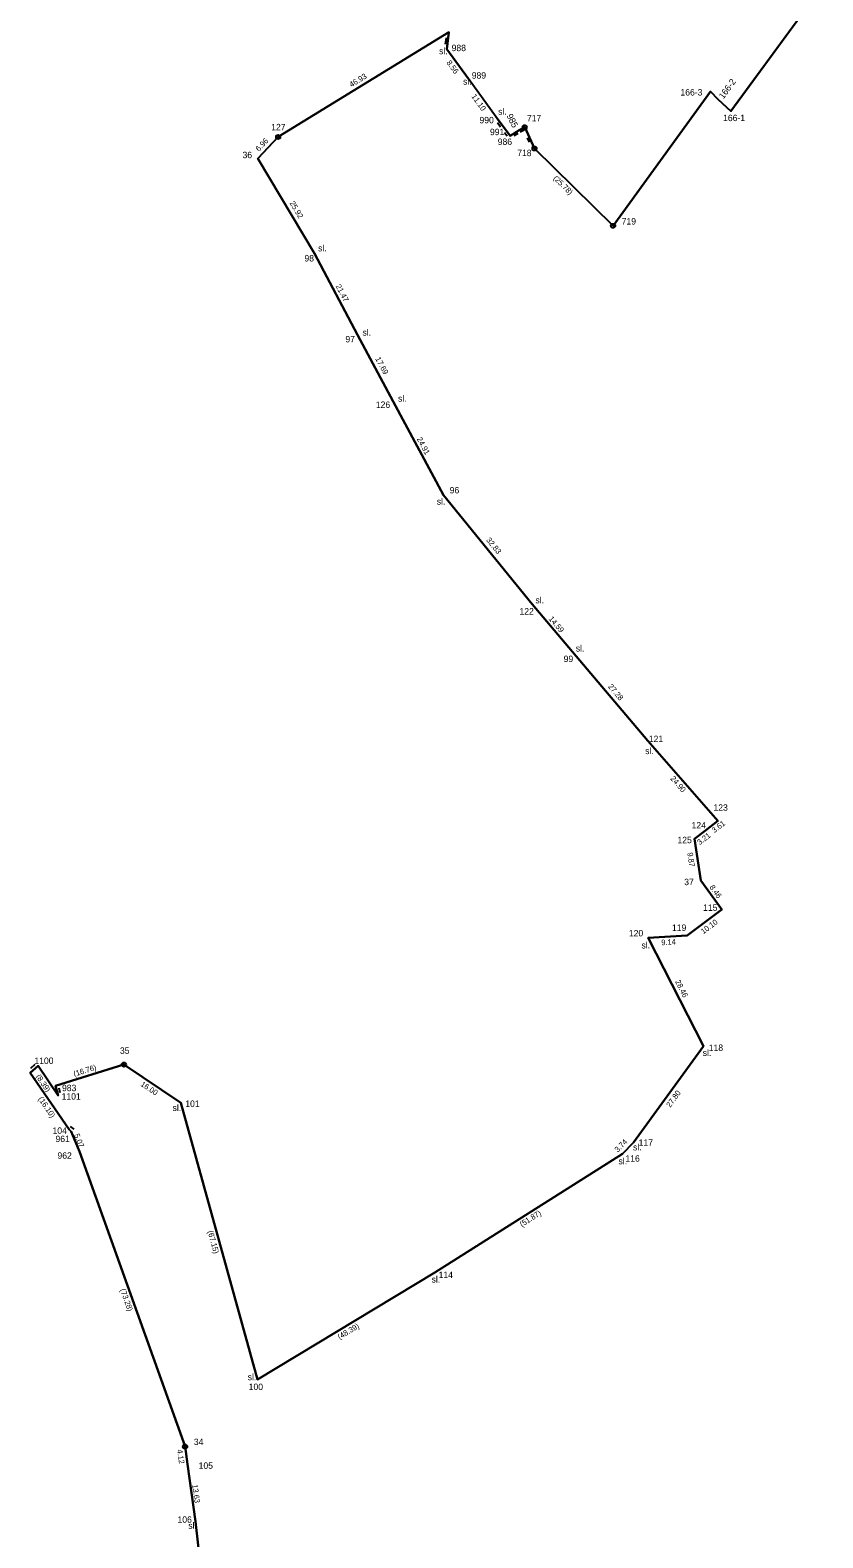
# Model space of a CAD drawing. Extents: x -555170 to -550532, y -1039598 to -1034701.
# Drawn here: x -553408.5 to -553223.3, y -1037142.8 to -1036790.2 of the extents above; entities that cross this region are included whole.
import ezdxf

# ---------------------------------------------------------------- set-up
doc = ezdxf.new("R2010")
doc.units = 0
for name, color, linetype in [('Vrstva 10', 7, 'Continuous'), ('Vrstva 40', 7, 'Continuous'), ('Vrstva 43', 7, 'Continuous'), ('Vrstva 48', 7, 'Continuous')]:
    doc.layers.add(name, color=color, linetype=linetype)

msp = doc.modelspace()

# ---------------------------------------------------------------- linework, layer by layer
at = {"layer": 'Vrstva 10'}
for p, q in [((-553311.34, -1036792.05), (-553311.51, -1036793.49)), ((-553299.35, -1036811.86), (-553298.6, -1036812.89)), ((-553297.7, -1036814.18), (-553297.09, -1036814.97)), ((-553294.55, -1036814.4), (-553295.49, -1036814.99)), ((-553293.06, -1036813.64), (-553293.98, -1036814.12)), ((-553292.37, -1036815.42), (-553291.94, -1036816.44)), ((-553407.46, -1037032.17), (-553408.45, -1037033.06)), ((-553401.8, -1037037.58), (-553401.57, -1037038.7)), ((-553398.25, -1037047.28), (-553399.1, -1037046.63))]:
    msp.add_line(p, q, dxfattribs=at)
at = {"layer": 'Vrstva 40'}
for p, q in [((-553244.82, -1036809.16), (-553223.29, -1036779.77)), ((-553350.57, -1036815.23), (-553310.65, -1036790.68)), ((-553310.65, -1036790.68), (-553311.17, -1036794.7)), ((-553311.17, -1036794.7), (-553306.11, -1036801.6)), ((-553299.66, -1036810.61), (-553306.11, -1036801.6)), ((-553272.29, -1036836), (-553249.53, -1036804.61)), ((-553249.53, -1036804.61), (-553247.71, -1036806.46)), ((-553247.71, -1036806.46), (-553244.82, -1036809.16)), ((-553299.66, -1036810.61), (-553297.43, -1036813.48)), ((-553297.43, -1036813.48), (-553296.32, -1036814.94)), ((-553296.32, -1036814.94), (-553294.28, -1036813.67)), ((-553294.28, -1036813.67), (-553292.96, -1036812.95)), ((-553292.96, -1036812.95), (-553290.67, -1036817.92)), ((-553355.33, -1036820.26), (-553350.57, -1036815.23)), ((-553290.67, -1036817.92), (-553272.29, -1036836)), ((-553342.08, -1036842.48), (-553355.33, -1036820.26)), ((-553332.03, -1036861.48), (-553342.08, -1036842.48)), ((-553323.67, -1036877.07), (-553332.03, -1036861.48)), ((-553311.9, -1036899.03), (-553323.67, -1036877.07)), ((-553291.24, -1036924.49), (-553311.9, -1036899.03)), ((-553281.81, -1036935.62), (-553291.24, -1036924.49)), ((-553264.19, -1036956.46), (-553281.81, -1036935.62)), ((-553247.82, -1036975.19), (-553264.19, -1036956.46)), ((-553250.7, -1036977.4), (-553247.82, -1036975.19)), ((-553253.25, -1036979.35), (-553250.7, -1036977.4)), ((-553251.83, -1036989.09), (-553253.25, -1036979.35)), ((-553246.86, -1036995.93), (-553251.83, -1036989.09)), ((-553254.96, -1037001.96), (-553246.86, -1036995.93)), ((-553264.1, -1037002.49), (-553254.96, -1037001.96)), ((-553251.2, -1037027.86), (-553264.1, -1037002.49)), ((-553267.5, -1037050.36), (-553251.2, -1037027.86)), ((-553408.52, -1037034.1), (-553406.66, -1037032.45)), ((-553406.66, -1037032.45), (-553401.96, -1037039.4)), ((-553402.62, -1037037.13), (-553386.61, -1037032.17)), ((-553386.61, -1037032.17), (-553373.33, -1037041.08)), ((-553399.41, -1037047.38), (-553408.52, -1037034.1)), ((-553401.96, -1037039.4), (-553402.62, -1037037.13)), ((-553373.33, -1037041.08), (-553355.37, -1037105.78)), ((-553398.91, -1037047.8), (-553399.41, -1037047.38)), ((-553397.02, -1037052.51), (-553398.91, -1037047.8)), ((-553270.12, -1037053.03), (-553267.5, -1037050.36)), ((-553372.33, -1037121.5), (-553397.02, -1037052.51)), ((-553313.92, -1037080.81), (-553270.12, -1037053.03)), ((-553355.37, -1037105.78), (-553313.92, -1037080.81)), ((-553371.74, -1037125.58), (-553372.33, -1037121.5)), ((-553369.86, -1037139.04), (-553371.74, -1037125.58)), ((-553368.67, -1037150.1), (-553369.86, -1037139.04))]:
    msp.add_line(p, q, dxfattribs=at)
at = {"layer": 'Vrstva 43'}
for p, q in [((-553310.65, -1036790.68), (-553310.65, -1036790.68)), ((-553311.17, -1036794.7), (-553311.17, -1036794.7)), ((-553306.11, -1036801.6), (-553306.11, -1036801.6)), ((-553249.53, -1036804.61), (-553249.53, -1036804.61)), ((-553247.71, -1036806.46), (-553247.71, -1036806.46)), ((-553299.66, -1036810.61), (-553299.66, -1036810.61)), ((-553244.82, -1036809.16), (-553244.82, -1036809.16)), ((-553297.43, -1036813.48), (-553297.43, -1036813.48)), ((-553294.28, -1036813.67), (-553294.28, -1036813.67)), ((-553292.96, -1036812.95), (-553292.96, -1036812.95)), ((-553350.57, -1036815.23), (-553350.57, -1036815.23)), ((-553296.32, -1036814.94), (-553296.32, -1036814.94)), ((-553290.67, -1036817.92), (-553290.67, -1036817.92)), ((-553355.33, -1036820.26), (-553355.33, -1036820.26)), ((-553272.29, -1036836), (-553272.29, -1036836)), ((-553342.08, -1036842.48), (-553342.08, -1036842.48)), ((-553332.03, -1036861.48), (-553332.03, -1036861.48)), ((-553323.67, -1036877.07), (-553323.67, -1036877.07)), ((-553311.9, -1036899.03), (-553311.9, -1036899.03)), ((-553291.24, -1036924.49), (-553291.24, -1036924.49)), ((-553281.81, -1036935.62), (-553281.81, -1036935.62)), ((-553264.19, -1036956.46), (-553264.19, -1036956.46)), ((-553247.82, -1036975.19), (-553247.82, -1036975.19)), ((-553253.25, -1036979.35), (-553253.25, -1036979.35)), ((-553250.7, -1036977.4), (-553250.7, -1036977.4)), ((-553251.83, -1036989.09), (-553251.83, -1036989.09)), ((-553246.86, -1036995.93), (-553246.86, -1036995.93)), ((-553264.1, -1037002.49), (-553264.1, -1037002.49)), ((-553254.96, -1037001.96), (-553254.96, -1037001.96)), ((-553251.2, -1037027.86), (-553251.2, -1037027.86)), ((-553406.66, -1037032.45), (-553406.66, -1037032.45)), ((-553386.61, -1037032.17), (-553386.61, -1037032.17)), ((-553408.52, -1037034.1), (-553408.52, -1037034.1)), ((-553402.62, -1037037.13), (-553402.62, -1037037.13)), ((-553401.96, -1037039.4), (-553401.96, -1037039.4)), ((-553373.33, -1037041.08), (-553373.33, -1037041.08)), ((-553399.41, -1037047.38), (-553399.41, -1037047.38)), ((-553398.91, -1037047.8), (-553398.91, -1037047.8)), ((-553267.5, -1037050.36), (-553267.5, -1037050.36)), ((-553397.02, -1037052.51), (-553397.02, -1037052.51)), ((-553270.12, -1037053.03), (-553270.12, -1037053.03)), ((-553313.92, -1037080.81), (-553313.92, -1037080.81)), ((-553355.37, -1037105.78), (-553355.37, -1037105.78)), ((-553372.33, -1037121.5), (-553372.33, -1037121.5)), ((-553371.74, -1037125.58), (-553371.74, -1037125.58)), ((-553369.86, -1037139.04), (-553369.86, -1037139.04))]:
    msp.add_line(p, q, dxfattribs=at)
for centre, radius in [((-553292.96, -1036812.95), 0.5), ((-553292.96, -1036812.95), 0.01), ((-553350.57, -1036815.23), 0.5), ((-553350.57, -1036815.23), 0.01), ((-553290.67, -1036817.92), 0.5), ((-553290.67, -1036817.92), 0.01), ((-553272.29, -1036836), 0.5), ((-553272.29, -1036836), 0.01), ((-553386.61, -1037032.17), 0.5), ((-553386.61, -1037032.17), 0.01), ((-553372.33, -1037121.5), 0.5), ((-553372.33, -1037121.5), 0.01)]:
    msp.add_circle(centre, radius, dxfattribs=at)
at = {"layer": 'Vrstva 48'}
msp.add_lwpolyline([(-553223.29, -1036779.77), (-553244.82, -1036809.16), (-553247.71, -1036806.46), (-553249.53, -1036804.61), (-553272.29, -1036836), (-553290.67, -1036817.92), (-553292.96, -1036812.95), (-553294.28, -1036813.67), (-553296.32, -1036814.94), (-553297.43, -1036813.48), (-553299.66, -1036810.61), (-553306.11, -1036801.6), (-553311.17, -1036794.7), (-553310.65, -1036790.68), (-553350.57, -1036815.23), (-553355.33, -1036820.26), (-553342.08, -1036842.48), (-553332.03, -1036861.48), (-553323.67, -1036877.07), (-553311.9, -1036899.03), (-553291.24, -1036924.49), (-553281.81, -1036935.62), (-553264.19, -1036956.46), (-553247.82, -1036975.19), (-553250.7, -1036977.4), (-553253.25, -1036979.35), (-553251.83, -1036989.09), (-553246.86, -1036995.93), (-553254.96, -1037001.96), (-553264.1, -1037002.49), (-553251.2, -1037027.86), (-553267.5, -1037050.36), (-553270.12, -1037053.03), (-553313.92, -1037080.81), (-553355.37, -1037105.78), (-553373.33, -1037041.08), (-553386.61, -1037032.17), (-553402.62, -1037037.13), (-553401.96, -1037039.4), (-553406.66, -1037032.45), (-553408.52, -1037034.1), (-553399.41, -1037047.38), (-553398.91, -1037047.8), (-553397.02, -1037052.51), (-553372.33, -1037121.5), (-553371.74, -1037125.58), (-553369.86, -1037139.04), (-553368.67, -1037150.1)], dxfattribs=at)

# ---------------------------------------------------------------- texts
at = {"layer": 'Vrstva 10'}
for s, rotation, p in [('8.56', 306.2538, (-553311.32, -1036797.88)), ('46.93', 31.5907, (-553333.43, -1036803.65)), ('11.10', 305.5978, (-553305.48, -1036805.75)), ('6.96', 46.5798, (-553355.06, -1036818.7)), ('(25.78)', 315.4734, (-553286.39, -1036825.01)), ('25.92', 300.808, (-553347.94, -1036830.7)), ('21.47', 297.8765, (-553337.18, -1036850.1)), ('17.69', 298.202, (-553327.92, -1036867.09)), ('24.91', 298.1902, (-553318.23, -1036885.85)), ('32.83', 309.0583, (-553302.05, -1036909.53)), ('14.59', 310.2733, (-553287.44, -1036927.97)), ('27.28', 310.2142, (-553273.57, -1036943.82)), ('24.90', 311.1534, (-553259.01, -1036965.35)), ('3.61', 37.5012, (-553248.64, -1036978.07)), ('3.21', 37.4054, (-553252.05, -1036980.89)), ('9.87', 278.2946, (-553254.96, -1036982.65)), ('8.46', 306.0025, (-553249.85, -1036990.71)), ('10.10', 36.6656, (-553251.2, -1037001.71)), ('9.14', 3.3187, (-553261, -1037004.26)), ('28.46', 296.9522, (-553257.85, -1037012.75)), ('(16.76)', 17.2133, (-553398.19, -1037034.99)), ('(8.39)', 304.0793, (-553407.27, -1037034.97)), ('16.00', 326.141, (-553382.85, -1037037.04)), ('(16.10)', 304.46, (-553406.72, -1037040.21)), ('27.80', 54.0788, (-553258.95, -1037042.31)), ('5.07', 291.9377, (-553398.3, -1037048.62)), ('3.74', 45.5415, (-553271.19, -1037052.78)), ('(51.87)', 32.3848, (-553293.6, -1037070.19)), ('(67.15)', 285.5141, (-553367.06, -1037071.18)), ('(73.28)', 289.6899, (-553387.53, -1037084.81)), ('(48.39)', 31.0653, (-553336.2, -1037096.51)), ('4.12', 278.2284, (-553374.19, -1037122.27)), ('13.63', 277.9512, (-553370.68, -1037130.45))]:
    msp.add_text(s, height=1.3, rotation=rotation, dxfattribs=at).set_placement(p)
at = {"layer": 'Vrstva 43'}
for s, p in [('sl.', (-553312.96, -1036795.87)), ('988', (-553310.03, -1036795.15)), ('989', (-553305.33, -1036801.58)), ('sl.', (-553307.36, -1036803)), ('166-3', (-553256.56, -1036805.53)), ('990', (-553303.52, -1036812.03)), ('sl.', (-553299.17, -1036810.04)), ('717', (-553292.44, -1036811.58)), ('166-1', (-553246.59, -1036811.52)), ('127', (-553352.19, -1036813.66)), ('991', (-553301.07, -1036814.8)), ('986', (-553299.26, -1036817.09)), ('36', (-553358.9, -1036820.18)), ('718', (-553294.7, -1036819.71)), ('719', (-553270.29, -1036835.7)), ('sl.', (-553341.23, -1036841.98)), ('98', (-553344.43, -1036844.34)), ('sl.', (-553330.86, -1036861.68)), ('97', (-553334.86, -1036863.25)), ('126', (-553327.74, -1036878.59)), ('sl.', (-553322.56, -1036877.14)), ('96', (-553310.48, -1036898.58)), ('sl.', (-553313.5, -1036901.22)), ('sl.', (-553290.44, -1036924.29)), ('122', (-553294.17, -1036926.91)), ('sl.', (-553281.01, -1036935.56)), ('99', (-553283.85, -1036938.03)), ('121', (-553263.95, -1036956.74)), ('sl.', (-553264.8, -1036959.55)), ('123', (-553248.84, -1036972.8)), ('124', (-553253.96, -1036976.95)), ('125', (-553257.26, -1036980.39)), ('37', (-553255.68, -1036990.2)), ('115', (-553251.27, -1036996.21)), ('120', (-553268.61, -1037002.18)), ('119', (-553258.54, -1037000.9)), ('sl.', (-553265.66, -1037005.01)), ('35', (-553387.54, -1037029.65)), ('sl.', (-553251.36, -1037030.16)), ('118', (-553249.94, -1037028.97)), ('1100', (-553407.53, -1037032.01)), ('1101', (-553401.17, -1037040.36)), ('983', (-553401.08, -1037038.38)), ('sl.', (-553375.24, -1037043.03)), ('101', (-553372.27, -1037042.06)), ('104', (-553403.3, -1037048.37)), ('961', (-553402.61, -1037050.29)), ('117', (-553266.33, -1037051.16)), ('962', (-553402.14, -1037054.19)), ('sl.', (-553271.03, -1037055.49)), ('116', (-553269.41, -1037054.87)), ('sl.', (-553267.64, -1037052.24)), ('sl.', (-553314.72, -1037083.14)), ('114', (-553313.07, -1037082.09)), ('sl.', (-553357.69, -1037105.98)), ('100', (-553357.46, -1037108.27)), ('34', (-553370.26, -1037121.14)), ('105', (-553369.15, -1037126.7)), ('106', (-553374.09, -1037139.32)), ('sl.', (-553371.57, -1037140.73))]:
    msp.add_text(s, height=1.5, dxfattribs=at).set_placement(p)
for s, rotation, p in [('166-2', 54, (-553246.52, -1036806.46)), ('985', 297, (-553297.26, -1036810.26))]:
    msp.add_text(s, height=1.5, rotation=rotation, dxfattribs=at).set_placement(p)

doc.saveas('drawing.dxf')
